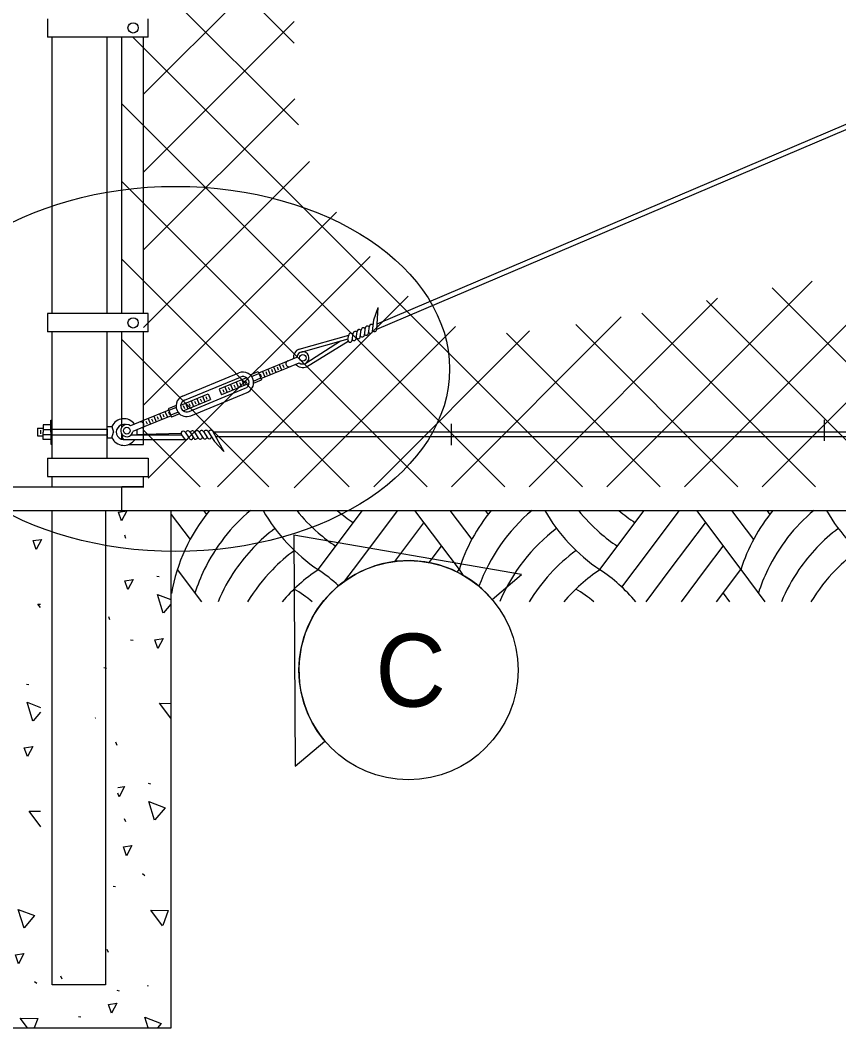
# Model space of a CAD drawing. Extents: x 99862 to 104211, y 98939 to 105076.
# Drawn here: x 102000.8 to 102224.9, y 101138.4 to 101414.3 of the extents above; entities that cross this region are included whole.
import ezdxf

# ---------------------------------------------------------------- set-up
doc = ezdxf.new("R2010")
doc.units = 0
for name, color, linetype in [('Level 10', 7, 'Continuous'), ('Level 11', 7, 'Continuous'), ('Level 2', 7, 'Continuous'), ('Level 20', 7, 'Continuous'), ('Level 4', 7, 'Continuous'), ('Level 6', 7, 'Continuous'), ('Level 7', 7, 'Continuous'), ('Level 9', 7, 'Continuous')]:
    doc.layers.add(name, color=color, linetype=linetype)

msp = doc.modelspace()

# ---------------------------------------------------------------- linework, layer by layer
at = {"layer": 'Level 10'}
for p, q in [((102042.14, 101280.06), (102706.43, 101280.06)), ((102042.14, 101278.95), (102047.29, 101272.08)), ((102050.94, 101280.06), (102051.76, 101278.97)), ((102082.38, 101263.86), (102094.54, 101280.06)), ((102092.02, 101263.86), (102104.18, 101280.06)), ((102108.79, 101280.06), (102120.95, 101263.86)), ((102118.43, 101280.06), (102124.42, 101272.08)), ((102128.08, 101280.06), (102128.89, 101278.97)), ((102159.51, 101263.86), (102171.67, 101280.06)), ((102169.16, 101263.86), (102181.31, 101280.06)), ((102185.93, 101280.06), (102198.08, 101263.86)), ((102195.57, 101280.06), (102201.55, 101272.08)), ((102205.21, 101280.06), (102206.03, 101278.97)), ((102103.34, 101266.09), (102111.31, 101276.71)), ((102178.8, 101263.86), (102188.44, 101276.71)), ((102112.75, 101265.79), (102116.13, 101270.28)), ((102188.44, 101263.86), (102193.26, 101270.28)), ((102043.81, 101263.86), (102050.4, 101255.07)), ((102089.71, 101260.78), (102092.02, 101263.86)), ((102120.45, 101263.19), (102120.95, 101263.86)), ((102120.95, 101263.86), (102122.12, 101262.29)), ((102165.56, 101259.06), (102169.16, 101263.86)), ((102172.21, 101255.07), (102178.8, 101263.86)), ((102181.85, 101255.07), (102188.44, 101263.86)), ((102191.49, 101255.07), (102198.08, 101263.86)), ((102198.08, 101263.86), (102204.67, 101255.07)), ((102193.26, 101257.43), (102195.03, 101255.07))]:
    msp.add_line(p, q, dxfattribs=at)
for centre, start, end in [((102090.32, 101249.06), 140.5627, 170.2714), ((102095.14, 101242.64), 129.9188, 154.2266), ((102109.6, 101304.36), 209.8569, 236.0964), ((102114.42, 101310.79), 219.0175, 228.9599), ((102119.24, 101317.21), 229.5771, 236.0964), ((102167.45, 101249.06), 140.5627, 162.3566), ((102172.27, 101242.64), 129.9188, 160.0496), ((102186.74, 101304.36), 209.8569, 236.0964), ((102191.56, 101310.79), 219.0175, 228.9599), ((102196.38, 101317.21), 229.5771, 236.0964), ((102244.59, 101249.06), 140.5627, 162.3566), ((102249.41, 101242.64), 129.9188, 154.2266), ((102263.87, 101304.36), 209.8569, 236.0964), ((102099.96, 101236.21), 127.1006, 145.4911), ((102177.09, 101236.21), 127.1006, 157.1246), ((102254.23, 101236.21), 127.1006, 145.4911), ((102114.42, 101310.79), 228.9599, 236.0964), ((102191.55, 101310.79), 228.9599, 236.0964), ((102104.78, 101229.78), 126.331, 135.7128), ((102181.91, 101229.78), 126.331, 148.7846), ((102259.05, 101229.78), 126.331, 135.7128), ((102095.14, 101242.64), 154.2265, 162.3566), ((102099.96, 101236.21), 145.491, 157.2609), ((102104.78, 101229.78), 135.7127, 148.7846), ((102109.6, 101223.35), 123.9036, 139.4601), ((102055.16, 101223.35), 47.7169, 56.0963), ((102186.74, 101223.35), 123.9036, 139.4601), ((102132.29, 101223.35), 40.5399, 56.0963), ((102249.41, 101242.64), 154.2265, 162.3566), ((102254.23, 101236.21), 145.491, 157.2609), ((102259.05, 101229.78), 135.7127, 148.7846), ((102050.34, 101216.93), 51.4164, 58.5465), ((102127.47, 101216.93), 51.4164, 58.5465)]:
    msp.add_arc(centre, 48.8, start, end, dxfattribs=at)
at = {"layer": 'Level 11'}
msp.add_ellipse((102043.36, 101318.82), major_axis=(-75, 0), ratio=0.666667, dxfattribs=at)
at = {"layer": 'Level 2'}
for p, q in [((102098.43, 101329.75), (102369.62, 101445.12)), ((102098.51, 101331.2), (102367.96, 101445.83)), ((102097.64, 101332.23), (102098.77, 101335.64)), ((102098.42, 101329.63), (102098.77, 101335.64)), ((102095.03, 101328.04), (102095.3, 101330.13)), ((102096.14, 101328.54), (102096.39, 101330.51)), ((102097.26, 101329.04), (102097.64, 101332.23)), ((102077.17, 101324.27), (102090.77, 101328.04)), ((102090.54, 101326.93), (102090.77, 101328.04)), ((102091.71, 101326.66), (102091.93, 101328.59)), ((102092.82, 101327.13), (102093.05, 101329.09)), ((102093.92, 101327.58), (102094.17, 101329.56)), ((102077.75, 101323.46), (102090.57, 101327.09)), ((102079.03, 101320.41), (102088.5, 101326.51)), ((102079.23, 101319.44), (102090.59, 101326.45)), ((102073.26, 101320.71), (102076.55, 101322.07)), ((102066.09, 101317.75), (102073.26, 101320.71)), ((102066.72, 101316.21), (102073.9, 101319.17)), ((102070.18, 101319.44), (102070.82, 101317.9)), ((102071.11, 101319.37), (102071.43, 101318.6)), ((102071.72, 101320.08), (102072.36, 101318.54)), ((102072.65, 101320.01), (102072.97, 101319.24)), ((102073.9, 101319.17), (102077.18, 101320.53)), ((102045.27, 101311.39), (102060.67, 101317.76)), ((102045.75, 101310.24), (102061.15, 101316.61)), ((102062.8, 101316.39), (102055.31, 101313.29)), ((102063.74, 101317.23), (102065.93, 101318.13)), ((102065.93, 101318.13), (102066.88, 101315.82)), ((102066.49, 101317.46), (102066.81, 101316.69)), ((102067.1, 101318.17), (102067.74, 101316.63)), ((102068.03, 101318.1), (102068.35, 101317.33)), ((102068.64, 101318.8), (102069.28, 101317.26)), ((102069.57, 101318.74), (102069.89, 101317.97)), ((102047.02, 101307.16), (102062.43, 101313.53)), ((102063.44, 101314.85), (102055.95, 101311.75)), ((102056.85, 101313.93), (102057.49, 101312.39)), ((102057.78, 101313.86), (102058.1, 101313.09)), ((102058.39, 101314.56), (102059.03, 101313.02)), ((102059.32, 101314.5), (102059.64, 101313.73)), ((102059.93, 101315.2), (102060.57, 101313.66)), ((102060.86, 101315.13), (102061.18, 101314.36)), ((102061.47, 101315.84), (102062.11, 101314.3)), ((102062.4, 101315.77), (102062.72, 101315)), ((102064.7, 101314.92), (102066.88, 101315.82)), ((102044.74, 101308.92), (102052.23, 101312.02)), ((102047.5, 101306), (102062.91, 101312.38)), ((102049.15, 101310.74), (102049.79, 101309.2)), ((102050.69, 101311.38), (102051.33, 101309.84)), ((102051.62, 101311.31), (102051.94, 101310.54)), ((102052.23, 101312.02), (102052.87, 101310.48)), ((102055.31, 101313.29), (102055.95, 101311.75)), ((102056.24, 101313.22), (102056.56, 101312.45)), ((102043.47, 101308.85), (102041.29, 101307.94)), ((102041.29, 101307.94), (102042.25, 101305.63)), ((102045.38, 101307.38), (102052.87, 101310.48)), ((102045.46, 101308.77), (102045.78, 101308)), ((102046.07, 101309.47), (102046.71, 101307.93)), ((102047, 101309.4), (102047.32, 101308.63)), ((102047.61, 101310.11), (102048.25, 101308.57)), ((102048.54, 101310.04), (102048.86, 101309.27)), ((102050.08, 101310.68), (102050.4, 101309.91)), ((102041.45, 101307.56), (102034.28, 101304.59)), ((102042.09, 101306.02), (102034.92, 101303.05)), ((102035.82, 101305.23), (102036.46, 101303.69)), ((102037.36, 101305.87), (102038, 101304.33)), ((102038.29, 101305.8), (102038.61, 101305.03)), ((102038.9, 101306.5), (102039.54, 101304.97)), ((102039.83, 101306.44), (102040.15, 101305.67)), ((102040.44, 101307.14), (102041.08, 101305.6)), ((102041.37, 101307.08), (102041.69, 101306.31)), ((102044.43, 101306.54), (102042.25, 101305.63)), ((102005.53, 101302.58), (102005.53, 101300.5)), ((102005.53, 101302.58), (102007.06, 101302.58)), ((102007.06, 101303.56), (102007.06, 101301.54)), ((102025.9, 101303.1), (102026.38, 101301.54)), ((102034.3, 101304.6), (102031.01, 101303.24)), ((102034.94, 101303.06), (102031.65, 101301.7)), ((102035.21, 101304.53), (102035.53, 101303.76)), ((102036.75, 101305.16), (102037.07, 101304.4)), ((102005.53, 101300.5), (102007.06, 101300.5)), ((102006.34, 101302.06), (102006.34, 101301.02)), ((102007.04, 101300.84), (102009.17, 101300.84)), ((102007.06, 101299.52), (102007.06, 101301.54)), ((102007.07, 101302.23), (102009.17, 101302.23)), ((102009.5, 101302.37), (102024.57, 101302.37)), ((102024.57, 101300.7), (102009.5, 101300.7)), ((102024.57, 101302.37), (102024.57, 101300.7)), ((102025.9, 101299.98), (102026.38, 101301.54)), ((102031.12, 101300.76), (102045, 101300.76)), ((102031.17, 101300.82), (102034.62, 101300.92)), ((102034.62, 101300.92), (102044.84, 101301.23)), ((102045, 101300.76), (102045.7, 101299.82)), ((102045.98, 101301.53), (102047.03, 101299.83)), ((102047.22, 101301.59), (102048.3, 101299.85)), ((102048.45, 101301.65), (102049.55, 101299.9)), ((102049.69, 101301.7), (102050.86, 101299.87)), ((102050.94, 101301.73), (102052.05, 101299.99)), ((102052.21, 101301.75), (102053.97, 101298.94)), ((102053.56, 101301.71), (102056.53, 101296.25)), ((102053.62, 101301.61), (102684.85, 101301.61)), ((102054.32, 101300.31), (102684.08, 101300.31)), ((102029.38, 101299.51), (102046.12, 101299.51)), ((102053.97, 101298.94), (102056.53, 101296.25))]:
    msp.add_line(p, q, dxfattribs=at)
for points in [[(102064.14, 101316.78), (102066.14, 101317.61)], [(102064.67, 101315.52), (102066.67, 101316.35)], [(102043.51, 101308.25), (102041.51, 101307.42)], [(102044.03, 101306.99), (102042.03, 101306.16)], [(102009.17, 101301.54), (102009.17, 101303.56), (102007.06, 101303.56)], [(102009.17, 101303.56), (102009.17, 101304.81), (102009.48, 101304.81)], [(102009.17, 101299.52), (102009.17, 101298.27), (102009.48, 101298.27), (102009.48, 101304.81)], [(102024.57, 101302.58), (102024.57, 101303.1), (102025.9, 101303.1)], [(102009.17, 101301.54), (102009.17, 101299.52), (102007.06, 101299.52)], [(102024.57, 101300.5), (102024.57, 101299.98), (102025.9, 101299.98)]]:
    msp.add_lwpolyline(points, dxfattribs=at)
for centre in [(102078.2, 101321.85), (102030, 101301.92)]:
    msp.add_circle(centre, 0.916, dxfattribs=at)
for centre, radius, start, end in [((102094.77, 101329.49), 0.605, 36.1699, 172.965), ((102095.88, 101329.97), 0.605, 36.7927, 180.322), ((102096.99, 101330.44), 0.605, 38.1909, 172.8552), ((102091.37, 101328.01), 0.605, 28.7661, 176.7144), ((102092.54, 101328.52), 0.605, 36.3421, 173.4693), ((102093.33, 101327.72), 0.605, 216.3421, 359.0605), ((102093.65, 101329), 0.605, 35.2689, 175.7258), ((102094.44, 101328.2), 0.605, 216.2101, 0.322), ((102095.55, 101328.68), 0.605, 216.0905, 359.5302), ((102096.66, 101329.16), 0.605, 216.1693, 357.792), ((102097.82, 101329.67), 0.605, 209.8958, 356.7345), ((102091.11, 101326.75), 0.605, 162.4528, 355.3366), ((102092.22, 101327.23), 0.605, 216.3997, 357.0048), ((102078.2, 101321.85), 2.63, 113.1749, 183.9611), ((102078.2, 101321.85), 1.67, 232.4657, 172.4657), ((102074.37, 101320.27), 0.833, 112.4657, 292.4657), ((102078.2, 101321.85), 2.63, 220.9704, 293.1749), ((102061.79, 101315.07), 2.92, 8.942, 112.4677), ((102061.79, 101315.07), 1.67, 348.8072, 112.4675), ((102061.79, 101315.07), 1.67, 292.4657, 352.4644), ((102061.79, 101315.07), 2.92, 292.4657, 8.942), ((102046.39, 101308.7), 2.92, 112.4638, 217.9151), ((102046.39, 101308.7), 1.67, 112.464, 236.2929), ((102029.19, 101301.54), 3.64, 36.4533, 154.6231), ((102046.39, 101308.7), 2.92, 215.9905, 292.4657), ((102046.39, 101308.7), 1.67, 232.4657, 292.4657), ((102029.19, 101301.54), 2.08, 76.8651, 282.1296), ((102030, 101301.92), 1.67, 52.4657, 352.4657), ((102033.83, 101303.51), 0.833, 292.4657, 112.4657), ((102029.19, 101301.54), 3.64, 205.3769, 324.5603), ((102029.36, 101300.13), 0.625, 131.539, 271.7561), ((102029.19, 101301.54), 3.64, 347.6731, 10.0249), ((102045.46, 101301.18), 0.625, 29.9117, 222.7955), ((102046.25, 101300.12), 0.625, 208.5339, 356.4821), ((102046.71, 101301.22), 0.625, 28.2435, 168.8486), ((102047.57, 101300.16), 0.625, 211.779, 348.9062), ((102047.96, 101301.26), 0.625, 26.1878, 168.9062), ((102048.82, 101300.2), 0.625, 209.5225, 349.9794), ((102049.21, 101301.3), 0.625, 24.9263, 169.0382), ((102050.08, 101300.24), 0.625, 212.2833, 349.0784), ((102050.46, 101301.34), 0.625, 25.718, 169.1578), ((102051.33, 101300.28), 0.625, 204.9263, 348.4556), ((102051.71, 101301.38), 0.625, 27.4563, 169.079), ((102052.58, 101300.33), 0.625, 212.3931, 347.0574), ((102053.01, 101301.42), 0.625, 28.5138, 175.3525)]:
    msp.add_arc(centre, radius, start, end, dxfattribs=at)
at = {"layer": 'Level 4'}
for p, q in [((102075.82, 101408.06), (102028.58, 101455.3)), ((102034.59, 101394.05), (102075.82, 101435.25)), ((102076.95, 101385.65), (102028.58, 101434.02)), ((102034.59, 101372.74), (102075.82, 101413.96)), ((102154.72, 101286.58), (102031.61, 101409.71)), ((102133.46, 101286.58), (102028.58, 101391.47)), ((102034.59, 101351.46), (102075.95, 101392.82)), ((102034.59, 101330.19), (102080.02, 101375.61)), ((102112.18, 101286.58), (102028.58, 101370.18)), ((102034.59, 101308.9), (102087.44, 101361.74)), ((102035.85, 101288.88), (102096.62, 101349.65)), ((102203.98, 101286.58), (102267.2, 101349.8)), ((102090.9, 101286.58), (102028.58, 101348.91)), ((102182.69, 101286.58), (102242.28, 101346.17)), ((102161.41, 101286.58), (102217.67, 101342.84)), ((102054.82, 101286.58), (102107.04, 101338.79)), ((102261.13, 101286.58), (102206.69, 101341.02)), ((102140.14, 101286.58), (102191.76, 101338.2)), ((102239.68, 101286.58), (102188.72, 101337.6)), ((102118.85, 101286.58), (102165.33, 101333.06)), ((102218.57, 101286.58), (102171.03, 101334.12)), ((102075.82, 101286.27), (102120.01, 101330.45)), ((102197.29, 101286.58), (102152.91, 101330.96)), ((102097.58, 101286.58), (102140.27, 101329.28)), ((102176.01, 101286.58), (102133.94, 101328.66)), ((102068.84, 101286.58), (102028.58, 101326.85)), ((102118.76, 101303.78), (102118.76, 101297.99)), ((102220.91, 101304.93), (102220.91, 101299.12)), ((102050.06, 101286.58), (102034.59, 101302.05))]:
    msp.add_line(p, q, dxfattribs=at)
at = {"layer": 'Level 6'}
for p, q in [((101992.04, 101280.06), (102042.14, 101280.06)), ((102042.14, 101138.38), (102042.14, 101280.06)), ((102029.74, 101272.43), (102029.41, 101273.29)), ((102038.22, 101262.09), (102038.88, 101261.96)), ((102025.37, 101250.1), (102025.04, 101250.95)), ((102031.03, 101244.65), (102031.69, 101244.52)), ((102023.73, 101237.04), (102024.38, 101236.91)), ((102002.49, 101232.53), (102003.15, 101232.4)), ((102027.34, 101215.72), (102027.01, 101216.57)), ((102035.83, 101205.38), (102036.48, 101205.24)), ((102029.7, 101194.78), (102029.37, 101195.64)), ((102034.26, 101180.67), (102034.91, 101180.14)), ((102026.27, 101177.21), (102026.92, 101177.08)), ((102024.94, 101159), (102024.61, 101159.86)), ((102004.7, 101151.11), (102005.36, 101150.59)), ((102012.27, 101151.72), (102011.95, 101152.57)), ((102027.25, 101148.66), (102027.91, 101148.53)), ((102035.87, 101149.72), (102035.76, 101150.02)), ((102016.74, 101141.49), (102017.4, 101141.36)), ((101991.98, 101138.38), (102042.14, 101138.38))]:
    msp.add_line(p, q, dxfattribs=at)
for points in [[(102028.54, 101277.2), (102027.69, 101279.63), (102029.98, 101279.96), (102028.54, 101277.2)], [(102005.17, 101269.38), (102004.31, 101271.81), (102006.61, 101272.14), (102005.17, 101269.38)], [(102030.27, 101258.39), (102029.42, 101260.82), (102031.71, 101261.15), (102030.27, 101258.39)], [(102039.97, 101251.97), (102038.4, 101257.09), (102042.05, 101255.69)], [(102006.31, 101253.52), (102005.61, 101254.45), (102006.31, 101254.44)], [(102042.05, 101254.42), (102040.04, 101252.03)], [(102038.5, 101242.23), (102037.65, 101244.65), (102039.94, 101244.98), (102038.5, 101242.23)], [(102004.24, 101222.41), (102002.66, 101227.53), (102006.31, 101226.13)], [(102042.05, 101223.19), (102038.94, 101227.29), (102042.05, 101227.24)], [(102006.31, 101224.86), (102004.3, 101222.48)], [(102021.36, 101223.24), (102021.41, 101223.24), (102021.36, 101223.15)], [(102002.77, 101212.67), (102001.91, 101215.1), (102004.21, 101215.43), (102002.77, 101212.67)], [(102027.53, 101204.18), (102029.31, 101204.43), (102027.87, 101201.67)], [(102027.87, 101201.67), (102027.53, 101202.63)], [(102037.57, 101195.25), (102036, 101200.37), (102040.46, 101198.66), (102037.64, 101195.32)], [(102006.44, 101193.46), (102003.21, 101197.73), (102006.31, 101197.68)], [(102029.92, 101185.51), (102029.07, 101187.94), (102031.37, 101188.27), (102029.92, 101185.51)], [(102001.84, 101165.7), (102000.27, 101170.81), (102004.73, 101169.11), (102001.91, 101165.76)], [(102039.77, 101166.31), (102036.54, 101170.58), (102041.32, 101170.5), (102039.81, 101166.39)], [(102000.37, 101155.95), (101999.51, 101158.38), (102001.81, 101158.71), (102000.37, 101155.95)], [(102025.79, 101142.36), (102024.94, 101144.79), (102027.24, 101145.12), (102025.79, 101142.36)], [(102002.81, 101138.38), (102000.81, 101141.02), (102005.59, 101140.94), (102004.65, 101138.38)], [(102035.87, 101138.38), (102034.96, 101141.32), (102039.42, 101139.61), (102038.38, 101138.38)]]:
    msp.add_lwpolyline(points, dxfattribs=at)
at = {"layer": 'Level 7'}
for p, q in [((102008.26, 101414.73), (102008.26, 101409.71)), ((102035.85, 101409.71), (102035.85, 101414.73)), ((102035.85, 101409.71), (102008.26, 101409.71)), ((102009.52, 101358.56), (102009.52, 101409.71)), ((102024.56, 101342.5), (102024.56, 101409.71)), ((102028.58, 101358.56), (102028.58, 101409.71)), ((102034.59, 101358.56), (102034.59, 101409.71)), ((102009.52, 101342.5), (102009.52, 101358.56)), ((102028.58, 101342.5), (102028.58, 101358.56)), ((102034.59, 101342.5), (102034.59, 101358.56)), ((102009.52, 101333.98), (102009.52, 101342.5)), ((102024.56, 101333.98), (102024.56, 101342.5)), ((102028.58, 101333.98), (102028.58, 101342.5)), ((102034.59, 101333.98), (102034.59, 101342.5)), ((102035.85, 101333.98), (102008.26, 101333.98)), ((102008.26, 101333.98), (102008.26, 101328.96)), ((102035.85, 101328.96), (102035.85, 101333.98)), ((102034.59, 101328.96), (102008.26, 101328.96)), ((102009.52, 101294.36), (102009.52, 101328.96)), ((102024.56, 101294.36), (102024.56, 101328.96)), ((102028.58, 101302.79), (102028.58, 101328.96)), ((102035.85, 101328.96), (102034.59, 101328.96)), ((102034.59, 101298.1), (102034.59, 101328.96)), ((102028.58, 101299.55), (102028.58, 101301.05)), ((102030.4, 101298.1), (102034.59, 101298.1)), ((102008.26, 101294.36), (102035.85, 101294.36)), ((102008.26, 101294.36), (102008.26, 101289.34)), ((102035.85, 101294.36), (102035.85, 101289.34)), ((102008.26, 101289.34), (102035.85, 101289.34)), ((102009.52, 101286.58), (102009.52, 101289.34)), ((102034.59, 101286.58), (102034.59, 101289.34)), ((101984.46, 101286.58), (102034.61, 101286.58)), ((102034.59, 101286.58), (102028.58, 101286.58)), ((102028.6, 101280.06), (102028.6, 101286.58))]:
    msp.add_line(p, q, dxfattribs=at)
msp.add_lwpolyline([(102024.17, 101279.98), (102024.17, 101150.18), (102009.54, 101150.18), (102009.54, 101279.98)], dxfattribs=at)
for centre in [(102031.71, 101412.22), (102031.71, 101331.44)]:
    msp.add_circle(centre, 1.41, dxfattribs=at)
at = {"layer": 'Level 9'}
for p, q in [((102138.07, 101262.57), (102075.76, 101273.3)), ((102075.76, 101273.3), (102076.12, 101210.07)), ((102129.98, 101255.72), (102138.07, 101262.57)), ((102076.12, 101210.07), (102084.21, 101216.93))]:
    msp.add_line(p, q, dxfattribs=at)
msp.add_circle((102107.1, 101236.33), 30, dxfattribs=at)
msp.add_arc((102107.1, 101236.33), 30, 40.279, 220.2834, dxfattribs=at)

# ---------------------------------------------------------------- texts
at = {"layer": 'Level 20'}
msp.add_text('C', height=20, dxfattribs=at).set_placement((102098.04, 101226.33))

doc.saveas('drawing.dxf')
